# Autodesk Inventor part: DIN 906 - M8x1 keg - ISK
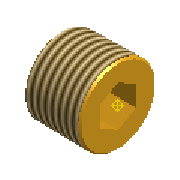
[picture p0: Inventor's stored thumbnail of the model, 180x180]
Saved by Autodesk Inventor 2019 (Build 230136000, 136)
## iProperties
Created: 2018-01
Part Number: DIN 906 - M8x1 keg - ISK
Material: Acier, doux
Description: Bouchon
Document SubType Name: Modeling
Standard: DIN 906
Designer: Thier
Standard Revision: 2012-04
Standards Organization: DIN
Language: fr-FR
Size Designation: M8x1 keg
Categories: <MemberInstance><Categories><Category DisplayName="Tubes et tuyaux" InternalName="4347fa0f-2144-441d-94cd-e3e15c92b736" Mnemonic="TUBEANDPIPE"><CategoryParamete
Mass: 4.24264 g
Surface Area: 4.58902 cm^2
Volume: 0.540464 cm^3
Density: 7.85 g/cm^3
Appearance: Semi-poli
IsCustomPart: 0
NAME: PIPING: Parker Countersunk Hex-Head Plug 219P
DATA: <meta><inlinegroups number="0" deflen="0"></inlinegroups><connections number="1"></connections><angles></angles></meta>
Author: Thier
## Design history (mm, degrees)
sketch "Sketch1"
  geometry: C1 r 4 at (0, 0); 1 further point
  constraints: 1 centre point, 1 coincident
  dimensions: "d0" = 8 diameter of C1 (= ND)
extrude "Extrusion1" new body sketch "Sketch1" distance "d1" = 8 (= L1); taper "d2" = -1 deg
chamfer "Chamfer1" distance "d3" = 0.5 (= 0.5 x PTC); stored, may be unused: second distance "d4" = 3.175, angle "d5" = 45 deg
sketch "Sketch2"
  geometry: L1 (0, 2.309)-(2, 1.155); L2 (2, 1.155)-(2, -1.155); L3 (2, -1.155)-(0, -2.309); L4 (0, -2.309)-(-2, -1.155); L5 (-2, -1.155)-(-2, 1.155); L6 (-2, 1.155)-(0, 2.309); C1 r 3.5 at (0, 0) reference; 1 further point
  constraints: 12 end point, 1 coincident, 1 vertical, 11 other
  dimensions: "d6" = 4 distance between parallel lines of L2 L5 (= C_HEX)
extrude "Extrusion2" cut sketch "Sketch2" distance "d7" = 4 (= T1); taper "d8" = 0 deg
sketch "Sketch3"
  geometry: L1 (-4, -2.55)-(-5.1, -2.55); L2 (-5.1, -2.55)-(-5.1, 0); L3 (-4, 0)-(-4, -2.55); L4 (-9.6, 0)-(1.6, 0) reference; L5 (-6.2, 0)-(-5.1, -1.1); L6 (-8, -3.36)-(-8, 3.36) reference; L7 (0, 3.5)-(0, -3.5) reference; L8 (-4, -1.155)-(-4, 1.155) reference; 1 further point
  constraints: 8 end point, 3 point on line, 1 horizontal, 1 midpoint, 1 parallel, 1 perpendicular
  dimensions: "d11" = 45 deg angle of L5 L4; "d12" = 1.8 distance from line of L6 L5.start (= W1); "d13" = 4 distance between parallel lines of L3 L7 (= T1); "d15" = 2.55 distance between parallel lines of L4 L1 (computed from C_HEX); "d16" = 1.1 distance between parallel lines of L2 L3 (= -0.5 x T1 - 0.5 x W1 + 0.5 x L1)
revolve "Revolution1" sketch "Sketch3" stored, may be unused: angle "d17" = 90 deg
sketch "Sketch4"
  geometry: L1 (0, -2)-(4, -2) reference; L2 (0, -2)-(0, -2.309); L3 (0, -3.5)-(0, 3.5) reference; L4 (0, -2.309)-(0.179, -2); L5 (0, 0)-(4, 0) reference
  constraints: 4 end point, 2 point on line
  dimensions: "d18" = 30 deg angle of L2 L4; "d19" = 2.3094 distance from line of L5 L2.end (= 0.57735 x C_HEX)
revolve "Revolution2" sketch "Sketch4" stored, may be unused: angle "d20" = 90 deg
workaxis "Work Axis1"
workpoint "Work Point1"
workaxis "Work Axis2"
workpoint "Work Point2"
body "Solid1"
feature "Filetage1" dims "d9" = 8 (= L1), "d10" = 0
other parameters: "C_HEX" = 4 [user parameter; used in 3 equation terms], "L1" = 8 [user parameter; used in 3 equation terms], "ND" = 8 [user parameter; used in 1 equation term], "PTC" = 1 [user parameter; used in 1 equation term], "T1" = 4 [user parameter; used in 3 equation terms], "W1" = 1.8 [user parameter; used in 2 equation terms], "Size_Designation" = 12.345 [user parameter]
